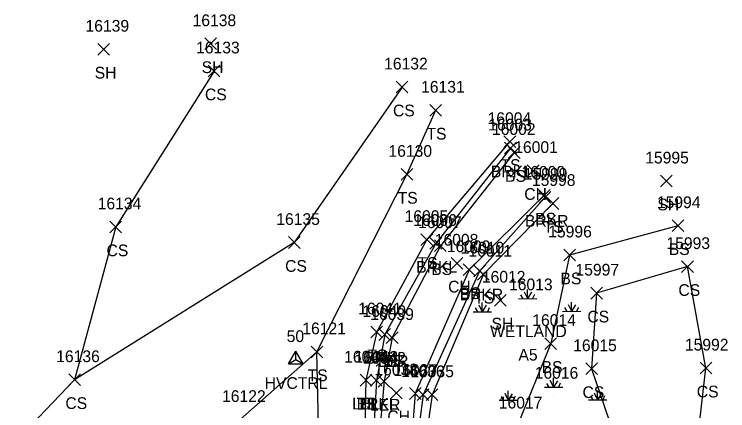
# Model space of a CAD drawing. Extents: x 1606530 to 1613020, y 784959 to 789666.
# Drawn here: x 1609253.6 to 1609375.3, y 788548 to 788615.7 of the extents above; entities that cross this region are included whole.
import ezdxf

# ---------------------------------------------------------------- set-up
doc = ezdxf.new("R2010")
doc.units = 0
for name, color, linetype in [('C_A', 7, 'Continuous'), ('C_I', 7, 'Continuous'), ('CPSM', 7, 'Continuous'), ('L_A', 7, 'Continuous'), ('L_C', 7, 'Continuous'), ('L_I', 7, 'Continuous'), ('L_TIC', 7, 'Continuous'), ('LARO', 7, 'Continuous'), ('LAWE', 7, 'Continuous'), ('LELB', 7, 'Continuous'), ('LWET', 7, 'Continuous')]:
    doc.layers.add(name, color=color, linetype=linetype)

msp = doc.modelspace()

# ---------------------------------------------------------------- linework, layer by layer
at = {"layer": 'CPSM'}
for p, q in [((1609300.37, 788556.04), (1609301.62, 788558.2)), ((1609302.87, 788556.04), (1609301.62, 788558.2)), ((1609301.62, 788556.76), (1609301.62, 788558.2)), ((1609300.37, 788556.04), (1609301.62, 788556.76)), ((1609300.37, 788556.04), (1609302.87, 788556.04)), ((1609301.62, 788556.76), (1609301.62, 788556.76)), ((1609301.62, 788556.76), (1609302.87, 788556.04))]:
    msp.add_line(p, q, dxfattribs=at)
at = {"layer": 'L_TIC'}
for points in [[(1609286.09, 788609.66), (1609288.09, 788611.66)], [(1609288.09, 788609.66), (1609286.09, 788611.66)], [(1609267.83, 788608.72), (1609269.83, 788610.72)], [(1609269.83, 788608.72), (1609267.83, 788610.72)], [(1609286.69, 788605.01), (1609288.69, 788607.01)], [(1609288.69, 788605.01), (1609286.69, 788607.01)], [(1609318.77, 788602.27), (1609320.77, 788604.27)], [(1609320.77, 788602.27), (1609318.77, 788604.27)], [(1609324.51, 788598.31), (1609326.51, 788600.31)], [(1609326.51, 788598.31), (1609324.51, 788600.31)], [(1609337.15, 788592.96), (1609339.15, 788594.96)], [(1609339.15, 788592.96), (1609337.15, 788594.96)], [(1609337.26, 788591.86), (1609339.26, 788593.86)], [(1609339.26, 788591.86), (1609337.26, 788593.86)], [(1609337.89, 788591.1), (1609339.89, 788593.1)], [(1609339.89, 788591.1), (1609337.89, 788593.1)], [(1609319.6, 788587.37), (1609321.6, 788589.37)], [(1609321.6, 788587.37), (1609319.6, 788589.37)], [(1609341.13, 788588.02), (1609343.13, 788590.02)], [(1609343.13, 788588.02), (1609341.13, 788590.02)], [(1609363.84, 788586.23), (1609365.84, 788588.23)], [(1609365.84, 788586.23), (1609363.84, 788588.23)], [(1609343.02, 788583.8), (1609345.02, 788585.8)], [(1609345.02, 788583.8), (1609343.02, 788585.8)], [(1609343.13, 788583.45), (1609345.13, 788585.45)], [(1609345.13, 788583.45), (1609343.13, 788585.45)], [(1609344.5, 788582.4), (1609346.5, 788584.4)], [(1609346.5, 788582.4), (1609344.5, 788584.4)], [(1609269.9, 788578.4), (1609271.9, 788580.4)], [(1609271.9, 788578.4), (1609269.9, 788580.4)], [(1609365.83, 788578.61), (1609367.83, 788580.61)], [(1609367.83, 788578.61), (1609365.83, 788580.61)], [(1609322.99, 788576.24), (1609324.99, 788578.24)], [(1609324.99, 788576.24), (1609322.99, 788578.24)], [(1609300.37, 788575.74), (1609302.37, 788577.74)], [(1609302.37, 788575.74), (1609300.37, 788577.74)], [(1609324.52, 788575.58), (1609326.52, 788577.58)], [(1609326.52, 788575.58), (1609324.52, 788577.58)], [(1609325.3, 788575.2), (1609327.3, 788577.2)], [(1609327.3, 788575.2), (1609325.3, 788577.2)], [(1609347.34, 788573.61), (1609349.34, 788575.61)], [(1609349.34, 788573.61), (1609347.34, 788575.61)], [(1609328.13, 788572.21), (1609330.13, 788574.21)], [(1609330.13, 788572.21), (1609328.13, 788574.21)], [(1609330.2, 788571.1), (1609332.2, 788573.1)], [(1609332.2, 788571.1), (1609330.2, 788573.1)], [(1609367.46, 788571.63), (1609369.46, 788573.63)], [(1609369.46, 788571.63), (1609367.46, 788573.63)], [(1609331.99, 788570.86), (1609333.99, 788572.86)], [(1609333.99, 788570.86), (1609331.99, 788572.86)], [(1609332.65, 788570.33), (1609334.65, 788572.33)], [(1609334.65, 788570.33), (1609332.65, 788572.33)], [(1609351.94, 788567.1), (1609353.94, 788569.1)], [(1609353.94, 788567.1), (1609351.94, 788569.1)], [(1609335.53, 788565.89), (1609337.53, 788567.89)], [(1609337.53, 788565.89), (1609335.53, 788567.89)], [(1609314.43, 788560.48), (1609316.43, 788562.48)], [(1609316.43, 788560.48), (1609314.43, 788562.48)], [(1609315.81, 788560.04), (1609317.81, 788562.04)], [(1609317.81, 788560.04), (1609315.81, 788562.04)], [(1609317.07, 788559.52), (1609319.07, 788561.52)], [(1609319.07, 788559.52), (1609317.07, 788561.52)], [(1609317.07, 788559.52), (1609319.07, 788561.52)], [(1609319.07, 788559.52), (1609317.07, 788561.52)], [(1609344.13, 788558.5), (1609346.13, 788560.5)], [(1609346.13, 788558.5), (1609344.13, 788560.5)], [(1609304.24, 788557.08), (1609306.24, 788559.08)], [(1609306.24, 788557.08), (1609304.24, 788559.08)], [(1609304.24, 788557.08), (1609306.24, 788559.08)], [(1609306.24, 788557.08), (1609304.24, 788559.08)], [(1609351.11, 788554.2), (1609353.11, 788556.2)], [(1609353.11, 788554.2), (1609351.11, 788556.2)], [(1609370.61, 788554.31), (1609372.61, 788556.31)], [(1609372.61, 788554.31), (1609370.61, 788556.31)], [(1609262.88, 788552.33), (1609264.88, 788554.33)], [(1609264.88, 788552.33), (1609262.88, 788554.33)], [(1609262.88, 788552.33), (1609264.88, 788554.33)], [(1609264.88, 788552.33), (1609262.88, 788554.33)], [(1609312.6, 788552.25), (1609314.6, 788554.25)], [(1609314.6, 788552.25), (1609312.6, 788554.25)], [(1609312.6, 788552.25), (1609314.6, 788554.25)], [(1609314.6, 788552.25), (1609312.6, 788554.25)], [(1609314.37, 788552.22), (1609316.37, 788554.22)], [(1609316.37, 788552.22), (1609314.37, 788554.22)], [(1609315.7, 788552.06), (1609317.7, 788554.06)], [(1609317.7, 788552.06), (1609315.7, 788554.06)], [(1609317.76, 788550.07), (1609319.76, 788552.07)], [(1609319.76, 788550.07), (1609317.76, 788552.07)], [(1609321.01, 788549.98), (1609323.01, 788551.98)], [(1609323.01, 788549.98), (1609321.01, 788551.98)], [(1609322.35, 788549.77), (1609324.35, 788551.77)], [(1609324.35, 788549.77), (1609322.35, 788551.77)], [(1609323.88, 788549.76), (1609325.88, 788551.76)], [(1609325.88, 788549.76), (1609323.88, 788551.76)]]:
    msp.add_lwpolyline(points, dxfattribs=at)
at = {"layer": 'LARO'}
for points in [[(1609318.07, 788560.52), (1609316.7, 788553.06), (1609315.72, 788542.33)], [(1609313.6, 788553.25), (1609313.34, 788542.78), (1609314.76, 788542.33), (1609315.72, 788542.33)]]:
    msp.add_lwpolyline(points, dxfattribs=at)
at = {"layer": 'LAWE'}
for points in [[(1609338.26, 788592.86), (1609325.52, 788576.58), (1609316.81, 788561.04), (1609315.37, 788553.22), (1609314.76, 788542.33), (1609313.61, 788524.98), (1609312.27, 788514.02), (1609308.3, 788506.2), (1609303.82, 788499.07), (1609298.93, 788492.77), (1609297.26, 788491.8), (1609294.18, 788489.58), (1609292.29, 788488.31), (1609291.48, 788483.29), (1609293.32, 788483.36)], [(1609344.13, 788584.45), (1609332.99, 788571.86), (1609323.35, 788550.77), (1609321.86, 788539.54), (1609326.22, 788524.89), (1609325, 788513.34), (1609315.19, 788503.57), (1609311.38, 788494.43), (1609306.34, 788485.87), (1609298.45, 788485.66), (1609293.32, 788483.36)]]:
    msp.add_lwpolyline(points, dxfattribs=at)
at = {"layer": 'LELB'}
for points in [[(1609287.69, 788606.01), (1609270.9, 788579.4), (1609263.88, 788553.33)], [(1609319.77, 788603.27), (1609301.37, 788576.74), (1609263.88, 788553.33), (1609243.1, 788531.64), (1609229.42, 788508.61), (1609200, 788494.81), (1609188, 788508.21), (1609183.65, 788514.97), (1609192.67, 788532.69), (1609206.54, 788560.83)], [(1609345.5, 788583.4), (1609333.65, 788571.33), (1609324.88, 788550.76), (1609323.31, 788539.55), (1609327.59, 788524.41), (1609326.06, 788512.92), (1609316.42, 788502.42), (1609312.43, 788493.74), (1609309.55, 788485.41), (1609300.66, 788483.19), (1609295.7, 788481.16), (1609290.69, 788481.42), (1609288.12, 788482.43), (1609286.78, 788487.09), (1609286.12, 788491), (1609287.42, 788500.95), (1609300.08, 788514.57), (1609305.81, 788532.99), (1609305.24, 788558.08), (1609320.6, 788588.37), (1609325.51, 788599.31)], [(1609338.15, 788593.96), (1609323.99, 788577.24), (1609315.43, 788561.48), (1609313.6, 788553.25)], [(1609338.89, 788592.1), (1609326.3, 788576.2), (1609318.07, 788560.52)], [(1609344.02, 788584.8), (1609331.2, 788572.1), (1609322.01, 788550.98), (1609321.14, 788539.89), (1609325.73, 788524.41), (1609324.19, 788513.38), (1609314.54, 788503.63), (1609310.99, 788495.08), (1609306, 788487.03), (1609297.1, 788486.9)], [(1609366.83, 788579.61), (1609348.34, 788574.61), (1609345.13, 788559.5), (1609339.41, 788545.41), (1609353.53, 788532.08), (1609355.9, 788515.93), (1609350.15, 788501.17), (1609342.75, 788489.3), (1609336.96, 788484.44), (1609343.27, 788499.19), (1609340.3, 788515.9), (1609331.63, 788517.32), (1609323.81, 788499.05), (1609313.67, 788488), (1609309.55, 788485.41)], [(1609368.31, 788526.35), (1609371.61, 788555.31), (1609368.46, 788572.63), (1609352.94, 788568.1), (1609352.11, 788555.2), (1609358.87, 788535.39)], [(1609305.24, 788558.08), (1609292.12, 788546.53), (1609272.3, 788525.77), (1609258.63, 788512.74), (1609243.89, 788498.47), (1609227.28, 788490.21), (1609208.03, 788485.11), (1609185.28, 788481.5)]]:
    msp.add_lwpolyline(points, dxfattribs=at)
at = {"layer": 'LWET'}
for p, q in [((1609340.57, 788568.34), (1609341.17, 788567.17)), ((1609341.16, 788567.16), (1609341.15, 788568.74)), ((1609341.83, 788568.25), (1609341.17, 788567.17)), ((1609339.61, 788567.15), (1609342.73, 788567.17)), ((1609339.96, 788567.79), (1609340.34, 788567.15)), ((1609342.33, 788567.85), (1609342.04, 788567.17)), ((1609332.84, 788566.12), (1609333.44, 788564.94)), ((1609333.43, 788564.93), (1609333.43, 788566.51)), ((1609334.11, 788566.03), (1609333.44, 788564.94)), ((1609348.08, 788566.18), (1609348.69, 788565)), ((1609348.68, 788564.99), (1609348.67, 788566.57)), ((1609349.35, 788566.09), (1609348.69, 788565)), ((1609331.88, 788564.93), (1609335.01, 788564.94)), ((1609332.23, 788565.57), (1609332.62, 788564.93)), ((1609333.49, 788565), (1609333.44, 788565)), ((1609334.6, 788565.62), (1609334.31, 788564.94)), ((1609341.16, 788565.59), (1609341.16, 788565.59)), ((1609347.13, 788564.98), (1609350.25, 788565)), ((1609347.48, 788565.63), (1609347.86, 788564.98)), ((1609348.73, 788565.05), (1609348.69, 788565.05)), ((1609349.85, 788565.68), (1609349.55, 788565)), ((1609345.6, 788552.06), (1609345.59, 788553.64)), ((1609344.39, 788552.7), (1609344.78, 788552.05)), ((1609345, 788553.25), (1609345.6, 788552.07)), ((1609346.27, 788553.15), (1609345.6, 788552.07)), ((1609346.76, 788552.75), (1609346.47, 788552.07)), ((1609337.87, 788549.84), (1609337.86, 788551.42)), ((1609344.04, 788552.05), (1609347.17, 788552.07)), ((1609353.11, 788549.9), (1609353.1, 788551.48)), ((1609336.66, 788550.47), (1609337.05, 788549.83)), ((1609337.27, 788551.03), (1609337.88, 788549.85)), ((1609338.54, 788550.93), (1609337.88, 788549.85)), ((1609337.92, 788549.9), (1609337.88, 788549.9)), ((1609339.04, 788550.53), (1609338.74, 788549.85)), ((1609345.6, 788550.5), (1609345.6, 788550.5)), ((1609351.56, 788549.89), (1609354.69, 788549.91)), ((1609351.91, 788550.53), (1609352.3, 788549.89)), ((1609352.52, 788551.08), (1609353.12, 788549.91)), ((1609353.79, 788550.99), (1609353.12, 788549.91)), ((1609353.16, 788549.96), (1609353.12, 788549.96)), ((1609354.28, 788550.59), (1609353.99, 788549.91)), ((1609336.32, 788549.83), (1609339.44, 788549.85))]:
    msp.add_line(p, q, dxfattribs=at)

# ---------------------------------------------------------------- texts
at = {"layer": 'C_A'}
msp.add_text('HVCTRL', height=2, dxfattribs=at).set_placement((1609296.32, 788551.76))
at = {"layer": 'C_I'}
msp.add_text('50', height=2, dxfattribs=at).set_placement((1609300.07, 788559.76))
at = {"layer": 'L_A'}
for s, p in [('SH', (1609285.57, 788605.66)), ('SH', (1609267.32, 788604.72)), ('CS', (1609286.13, 788601.01)), ('CS', (1609318.21, 788598.27)), ('TS', (1609323.92, 788594.31)), ('TS', (1609336.56, 788588.96)), ('BRKL', (1609334.91, 788587.86)), ('BS', (1609337.33, 788587.1)), ('TS', (1609319.01, 788583.37)), ('CH', (1609340.61, 788584.02)), ('SH', (1609363.33, 788582.23)), ('BS', (1609342.46, 788579.8)), ('BRKR', (1609340.72, 788579.45)), ('TS', (1609343.91, 788578.4)), ('CS', (1609269.34, 788574.4)), ('BS', (1609365.27, 788574.61)), ('TS', (1609322.4, 788572.24)), ('CS', (1609299.81, 788571.74)), ('BRKL', (1609322.17, 788571.58)), ('BS', (1609324.74, 788571.2)), ('BS', (1609346.78, 788569.61)), ('CH', (1609327.62, 788568.21)), ('CS', (1609366.91, 788567.63)), ('BRKR', (1609329.58, 788566.86)), ('BS', (1609329.64, 788567.1)), ('TS', (1609332.06, 788566.33)), ('CS', (1609351.38, 788563.1)), ('SH', (1609335.02, 788561.89)), ('WETLAND', (1609334.78, 788560.59)), ('TS', (1609313.84, 788556.48)), ('BRKL', (1609313.45, 788556.04)), ('LER', (1609315.65, 788555.52)), ('BS', (1609316.51, 788555.52)), ('BS', (1609343.57, 788554.5)), ('TS', (1609303.65, 788553.08)), ('TS', (1609303.65, 788553.08)), ('CS', (1609370.05, 788550.31)), ('CS', (1609350.55, 788550.2)), ('CS', (1609262.32, 788548.33)), ('CS', (1609262.32, 788548.33)), ('LEL', (1609311.24, 788548.25)), ('TS', (1609312.01, 788548.25)), ('BRKL', (1609312.01, 788548.22)), ('LER', (1609314.28, 788548.06)), ('CH', (1609317.25, 788546.07))]:
    msp.add_text(s, height=2, dxfattribs=at).set_placement(p)
at = {"layer": 'L_C'}
msp.add_text('A5', height=2, dxfattribs=at).set_placement((1609339.62, 788556.59))
at = {"layer": 'L_I'}
for s, p in [('16138', (1609284.02, 788613.66)), ('16139', (1609265.75, 788612.72)), ('16133', (1609284.62, 788609.01)), ('16132', (1609316.7, 788606.27)), ('16131', (1609323.01, 788602.31)), ('16004', (1609334.35, 788596.96)), ('16003', (1609334.47, 788595.86)), ('16002', (1609335.1, 788595.1)), ('16001', (1609338.9, 788592.02)), ('16130', (1609317.44, 788591.37)), ('15995', (1609361.25, 788590.23)), ('16000', (1609340.14, 788587.8)), ('15999', (1609340.53, 788587.45)), ('15998', (1609341.91, 788586.4)), ('16134', (1609267.83, 788582.4)), ('15994', (1609363.24, 788582.61)), ('16135', (1609298.3, 788579.74)), ('16005', (1609320.19, 788580.24)), ('16006', (1609321.67, 788579.58)), ('16007', (1609322.5, 788579.2)), ('15996', (1609344.7, 788577.61)), ('16008', (1609325.34, 788576.21)), ('16009', (1609327.4, 788575.1)), ('16010', (1609329.75, 788574.86)), ('15993', (1609364.87, 788575.63)), ('16011', (1609331.07, 788574.33)), ('15997', (1609349.35, 788571.1)), ('16012', (1609333.38, 788569.89)), ('16013', (1609338.01, 788568.59)), ('16041', (1609312.28, 788564.48)), ('16040', (1609313, 788564.04)), ('16039', (1609314.34, 788563.52)), ('16039', (1609314.34, 788563.52)), ('16014', (1609341.98, 788562.5)), ('16121', (1609302.74, 788561.08)), ('16121', (1609302.74, 788561.08)), ('16015', (1609348.96, 788558.2)), ('15992', (1609368.02, 788558.31)), ('16136', (1609260.75, 788556.33)), ('16136', (1609260.75, 788556.33)), ('16044', (1609309.88, 788556.25)), ('16044', (1609309.88, 788556.25)), ('16043', (1609311.65, 788556.22)), ('16042', (1609312.98, 788556.06)), ('16038', (1609315.04, 788554.07)), ('16037', (1609318.29, 788553.98)), ('16036', (1609319.58, 788553.77)), ('16035', (1609321.17, 788553.76)), ('16016', (1609342.39, 788553.5)), ('16122', (1609289.05, 788549.53)), ('16017', (1609336.26, 788548.41))]:
    msp.add_text(s, height=2, dxfattribs=at).set_placement(p)

doc.saveas('drawing.dxf')
